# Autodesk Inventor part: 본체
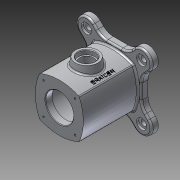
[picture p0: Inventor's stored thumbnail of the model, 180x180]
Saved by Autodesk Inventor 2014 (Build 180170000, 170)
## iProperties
Created: 2016-05
Part Number: 본체
Material: 알루미늄 6061
Document SubType Name: Modeling
Designer: S. S. MOON
Density: 2.71 g/cm^3
Appearance: 알루미늄 - 평지
Mass: 1114.45 g
Surface Area: 865.598 cm^2
Volume: 411.237 cm^3
Author: S. S. MOON
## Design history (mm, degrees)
sketch "스케치1" dims "d0" = 100
  geometry: L1 (35.355, 35.355)-(-35.355, 35.355); L2 (-35.355, 35.355)-(-35.355, -35.355); L3 (-35.355, -35.355)-(35.355, -35.355); L4 (35.355, -35.355)-(35.355, 35.355); A1 r 85.579 centre (0, -42.579) between (35.355, 35.355) and (-35.355, 35.355); A2 r 85.579 centre (-42.579, 0) between (35.355, -35.355) and (35.355, 35.355); A3 r 85.579 centre (0, 42.579) between (-35.355, -35.355) and (35.355, -35.355); A4 r 85.579 centre (42.579, 0) between (-35.355, 35.355) and (-35.355, -35.355); 4 further points
  constraints: 8 end point, 8 point on circle, 4 centre point, 3 equal radius, 2 midpoint, 2 parallel, 1 coincident, 1 horizontal, 1 horizontal alignment, 1 perpendicular, 1 vertical alignment, 3 other
  dimensions: "d3" = 86 dimension on A3 A1; "d4" = 86 dimension on A4 A2
extrude "돌출1" new body sketch "스케치1" stored distance "d5" = 98; taper "d6" = 0 deg
sketch "스케치2" dims "d11" = 70
  geometry: L1 (49, -49)-(-49, -49); L2 (-49, -49)-(-49, 49); L3 (-49, 49)-(49, 49); L4 (49, 49)-(49, -49); L5 (0, 0)-(49.497, -49.497); L6 (0, 98)-(0, -98) reference; L7 (62.225, -36.77)-(49, -23.544); L8 (36.77, -62.225)-(23.544, -49); A1 r 18 centre (49.497, -49.497) between (62.225, -36.77) and (36.77, -62.225); 3 further points
  constraints: 14 end point, 5 parallel, 2 coincident, 2 midpoint, 2 point on circle, 2 point on line, 2 tangent, 1 centre point, 1 horizontal, 1 horizontal alignment, 1 perpendicular, 1 vertical alignment, 3 other
  dimensions: "d7" = 98 distance of L2.end L3.end; "d9" = 45 deg angle of L6 L5; "d12" = 18 radius of A1
extrude "돌출2" join sketch "스케치2" distance "d13" = 12; taper "d14" = 0 deg
extrude "돌출3" join sketch "스케치2" distance "d15" = 12; taper "d16" = 0 deg
node "작업 평면1"
sketch "스케치4"
  geometry: 1 further point
hole "구멍1" sketch "스케치4" diameter "d18" = 50; stored, may be unused: countersink angle "d22" = 90 deg, drill point angle "d24" = 118 deg; dims "d19" = 6, "d20" = 70, "d21" = 43, "d23" = 8
hole "구멍2" sketch "스케치4" diameter "d25" = 50; stored, may be unused: countersink angle "d29" = 90 deg, drill point angle "d31" = 118 deg; dims "d26" = 6, "d27" = 70, "d28" = 43, "d30" = 8
hole "구멍6" diameter "d72" = 10; stored, may be unused: countersink angle "d76" = 90 deg, drill point angle "d78" = 118 deg; dims "d70" = 10, "d71" = 10, "d73" = 7, "d74" = 18, "d75" = 4, "d77" = 10
node "작업 평면2"
sketch "스케치5"
  geometry: C1 r 20 at (0, 0); 1 further point
  constraints: 1 centre point, 1 coincident
  dimensions: "d36" = 40 diameter of C1
extrude "돌출4" join sketch "스케치5" stored distance "d37" = 12; taper "d38" = 10 deg
hole "구멍3" diameter "d41" = 25; stored, may be unused: countersink angle "d45" = 90 deg, drill point angle "d47" = 118 deg; dims "d39" = 10, "d40" = 10, "d42" = 6, "d43" = 30, "d44" = 8, "d46" = 8
sketch "스케치7"
  geometry: L1 (0, 0)-(49.497, 49.497) reference; L2 (0, 0)-(28.284, 28.284); 1 further point
  constraints: 2 end point, 1 point on line
  dimensions: "d48" = 40 distance of L1.start L2.end
hole "구멍4" sketch "스케치7" at (28.284, 28.284) diameter "d49" = 3.242; stored, may be unused: countersink angle "d53" = 90 deg, drill point angle "d55" = 118 deg; dims "d50" = 7, "d51" = 30, "d52" = 8, "d54" = 10
sketch "스케치8"
  geometry: L1 (0, 0)-(49.497, -49.497) reference; L2 (0, 0)-(28.284, -28.284); 1 further point
  constraints: 2 end point, 1 point on line
  dimensions: "d59" = 40 distance of L1.start L2.end
hole "구멍5" sketch "스케치8" at (28.284, -28.284) diameter "d60" = 3.242; stored, may be unused: countersink angle "d64" = 90 deg, drill point angle "d66" = 118 deg; dims "d61" = 7, "d62" = 30, "d63" = 8, "d65" = 10
fillet "모깎기1" dims "d79" = 25
fillet "모깎기2" dims "d80" = 3
fillet "모깎기3" dims "d81" = 3
fillet "모깎기4" dims "d82" = 3
fillet "모깎기5" dims "d83" = 3
fillet "모깎기6" dims "d84" = 3
chamfer "모따기1" distance "d85" = 1; stored, may be unused: second distance "d86" = 2, angle "d87" = 45 deg
sketch "스케치11"
  geometry: L1 (-34.285, -49)-(34.285, -49) reference; 2 further points
  constraints: 1 other
  dimensions: "d90" = 29 distance of point (0, 0) point (29, 0); "d91" = 49 distance from line of L1 point (29, 0)
feature "엠보싱1" sketch "스케치11" dims "d0" = 100, "d3" = 86, "d4" = 86, "d7" = 98, "d9" = 45 deg, "d11" = 70, "d12" = 18, "d92" = 0.5, "d93" = 0
node "솔리드1"
pattern_circular "원형 패턴1" dims angle "d33" = 360 deg
pattern_circular "원형 패턴2" dims angle "d57" = 360 deg
pattern_circular "원형 패턴3" dims angle "d68" = 360 deg
other parameters: "d17" = -55, "d35" = 55
